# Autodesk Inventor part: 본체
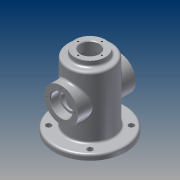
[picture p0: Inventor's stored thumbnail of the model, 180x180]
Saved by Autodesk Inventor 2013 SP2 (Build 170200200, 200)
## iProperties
Created: 2014-12
Part Number: 본체
Material: 알루미늄 6061
Document SubType Name: Modeling
Designer: CADB206
Density: 2.71 g/cm^3
Mass: 479.392 g
Surface Area: 605.402 cm^2
Volume: 176.898 cm^3
Author: CADB206
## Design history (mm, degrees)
sketch "스케치1"
  geometry: L1 (0, 43)-(0, -55); L2 (-27.5, -55)-(-52.5, -55); L3 (-52.5, -55)-(-52.5, -47); L4 (-52.5, -47)-(-32.5, -47); L5 (-32.5, -47)-(-32.5, 43); L6 (-32.5, 43)-(0, 43); L7 (-27.5, -55)-(-27.5, 38); L8 (-27.5, 38)-(0, 38); L9 (0, 0)-(-32.5, 0)
  constraints: 18 end point, 5 perpendicular, 3 parallel, 2 point on line, 1 horizontal alignment, 1 vertical, 1 vertical alignment
  dimensions: "d0" = 98 distance of L1.start L1.end; "d2" = 55 distance of L1.end L9.start; "d3" = 55 diameter of L7 L1; "d4" = 65 diameter of L5 L1; "d5" = 5 distance between parallel lines of L6 L8; "d6" = 105 diameter of L3 L1; "d7" = 5 distance between parallel lines of L7 L5 (derived); "d8" = 8 distance between parallel lines of L2 L4
revolve "회전1" stored, may be unused: angle "d9" = 90 deg
node "작업 평면1"
sketch "스케치2"
  geometry: L1 (-53, -27.5)-(-53, 27.5) reference; C1 r 25 at (2, 0); 1 further point
  constraints: 1 centre point, 1 coincident
  dimensions: "d10" = 50 diameter of C1; "d11" = 55 distance from line of L1 C1.centre
extrude "돌출1" join sketch "스케치2" stored distance "d12" = 10; taper "d13" = 0 deg
extrude "돌출2" join sketch "스케치2" distance "d14" = 10; taper "d15" = 0 deg
hole "구멍1" diameter "d18" = 25; stored, may be unused: countersink angle "d22" = 90 deg, drill point angle "d24" = 118 deg; dims "d16" = 10, "d17" = 10, "d19" = 6, "d20" = 32, "d21" = 12, "d23" = 20
chamfer "모따기1" distance "d25" = 1; stored, may be unused: second distance "d26" = 2, angle "d27" = 45 deg
sketch "스케치3"
  geometry: C1 r 25 at (0, 0) reference; C2 r 17 at (0, 0) reference; 2 further points
  constraints: 1 vertical alignment
  dimensions: "d28" = 20.5 distance of point (0, 0) point (0, 20.5)
hole "구멍2" sketch "스케치3" at (0, 20.5) diameter "d29" = 2.459; stored, may be unused: countersink angle "d33" = 90 deg, drill point angle "d35" = 118 deg; dims "d30" = 6, "d31" = 32, "d32" = 12, "d34" = 8
fillet "모깎기1" dims "d39" = 0.3
sketch "스케치4"
  geometry: C1 r 32.5 at (0, 0) reference; C2 r 22.5 at (0, 0); 1 further point
  constraints: 1 centre point, 1 coincident
  dimensions: "d40" = 45 diameter of C2
extrude "돌출3" join sketch "스케치4" distance "d41" = 8; taper "d42" = 0 deg
hole "구멍3" diameter "d45" = 27; stored, may be unused: countersink angle "d49" = 90 deg, drill point angle "d51" = 118 deg; dims "d43" = 10, "d44" = 10, "d46" = 6, "d47" = 32, "d48" = 12, "d50" = 8
sketch "스케치5"
  geometry: C1 r 13.5 at (0, 0) reference; C2 r 22.5 at (0, 0) reference; 2 further points
  constraints: 1 vertical alignment
  dimensions: "d52" = 17.5 distance of point (0, 17.5) point (0, 0)
hole "구멍4" sketch "스케치5" at (0, 17.5) diameter "d53" = 2.459; stored, may be unused: countersink angle "d57" = 90 deg, drill point angle "d59" = 118 deg; dims "d54" = 6, "d55" = 32, "d56" = 12, "d58" = 8
sketch "스케치6" dims "d64" = 86
  geometry: L1 (0, 0)-(37.123, 37.123); L2 (0, 0)-(52.5, 0); C1 r 22.5 at (0, 0) reference; C2 r 32.5 at (0, 0) reference; C3 r 32.5 at (0, 0) reference; C4 r 1.23 at (17.5, 0) reference; C5 r 1.23 at (0, -17.5) reference; C6 r 1.23 at (-17.5, 0) reference; C7 r 1.23 at (0, 17.5) reference; C8 r 13.5 at (0, 0) reference; C9 r 22.5 at (0, 0) reference; 4 further points
  constraints: 4 end point, 1 coincident, 1 equal length, 1 horizontal, 1 point on line, 5 other
  dimensions: "d63" = 45 deg angle of L2 L1
hole "구멍5" sketch "스케치6" at (30.406, 30.406) diameter "d65" = 8; stored, may be unused: countersink angle "d69" = 90 deg, drill point angle "d71" = 0 deg; dims "d66" = 6, "d67" = 32, "d68" = 12, "d70" = 8
chamfer "모따기2" distance "d75" = 1; stored, may be unused: second distance "d76" = 2, angle "d77" = 45 deg
fillet "모깎기2" dims "d78" = 3
fillet "모깎기3" dims "d79" = 3
fillet "모깎기4" dims "d80" = 3
fillet "모깎기5" dims "d81" = 3
node "솔리드1"
pattern_circular "원형 패턴1" dims angle "d37" = 360 deg
mirror "대칭1"
pattern_circular "원형 패턴2" dims angle "d61" = 360 deg
pattern_circular "원형 패턴3" dims angle "d73" = 360 deg
node "투영된 루프1"
node "투영된 루프2"
node "투영된 루프3"
node "투영된 루프4"
node "투영된 루프5"
node "투영된 루프6"
